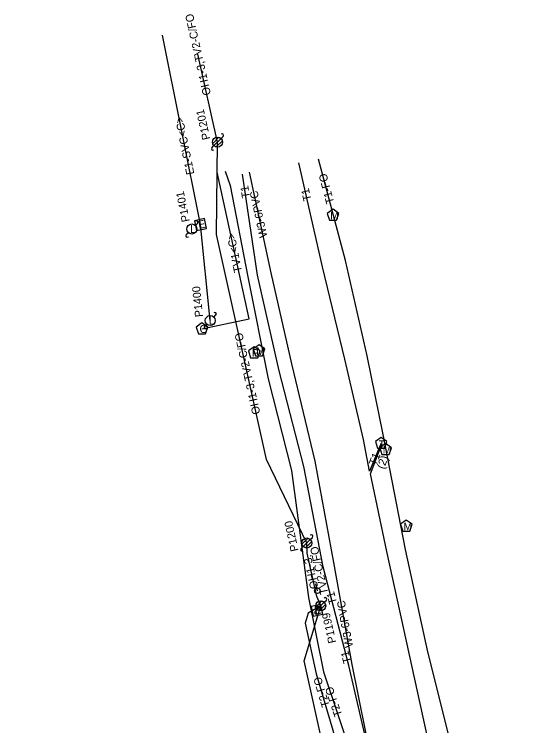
# Model space of a CAD drawing. Extents: x 2336688 to 2352634, y 362473 to 369571.
# Drawn here: x 2351896.3 to 2352159.1, y 369215.5 to 369570.9 of the extents above; entities that cross this region are included whole.
import ezdxf

# ---------------------------------------------------------------- set-up
doc = ezdxf.new("R2010")
doc.units = 0
for name, color, linetype in [('RD_EX_DV_Prop', 7, 'Continuous'), ('RD_EX_DV_TX_Prop', 7, 'Continuous'), ('RD_EX_RW', 7, 'Continuous'), ('RD_EX_RW_TX', 7, 'Continuous'), ('RD_HC_Data_Tic', 7, 'Continuous'), ('RD_PD_CstnLmt', 7, 'Continuous'), ('RD_PD_Final_TrvlWay', 7, 'Continuous'), ('RD_PD_PatLn4', 7, 'Continuous'), ('RD_SHT_ShtClip', 7, 'Continuous'), ('RD_Sketch2', 7, 'Continuous')]:
    doc.layers.add(name, color=color, linetype=linetype)

# ---------------------------------------------------------------- blocks, each defined once
blk = doc.blocks.new('GW')
at = {"layer": 'RD_HC_Data_Tic'}
blk.add_line((0, 0), (0, 5), dxfattribs=at)
blk.add_circle((0, 0), 2, dxfattribs=at)

msp = doc.modelspace()

# ---------------------------------------------------------------- linework, layer by layer
at = {"layer": 'RD_EX_RW_TX'}
for points in [[(2351882.96, 368961.6), (2351938.79, 368976.9), (2351987.72, 368987.57), (2352042.33, 368998.31), (2352089.62, 369005.75), (2352093.46, 369014.31), (2352094.98, 369015.98), (2352112.55, 369025.15), (2352149.58, 369043.65), (2352152.79, 369046.13), (2352158.47, 369042.65), (2352159.12, 369043.02), (2352158.82, 369043.5), (2352153.46, 369046.79), (2352149.48, 369061.78), (2352136.12, 369108.51), (2352124.11, 369157.73), (2352114.64, 369205.23), (2352102.73, 369252.4), (2352091.67, 369303.48), (2352080.48, 369361.01), (2352072.4, 369400.34), (2352061.58, 369447.94), (2352048.21, 369498.55)], [(2352099.24, 369013.18), (2352100.77, 369013.18), (2352102.01, 369010.35), (2352113.48, 369011.8), (2352144.5, 369021.33), (2352137.63, 369058.32), (2352126.61, 369104.63), (2352115.02, 369155.75), (2352104.18, 369202.36), (2352093.63, 369250.91), (2352082.32, 369302.6), (2352074.09, 369341.41), (2352079.44, 369355.35), (2352079.44, 369356.53), (2352079.15, 369355.79), (2352073.69, 369342.66), (2352070.62, 369358.43), (2352061.32, 369398.59), (2352050.18, 369444.73), (2352038.41, 369496.7)], [(2351989.99, 369413.72), (2352013.51, 369418.85), (2351997.53, 369492.08)], [(2352001.58, 369492.45), (2352004.02, 369485.34), (2352012.81, 369439.77), (2352023.11, 369388.83), (2352034.68, 369342.96), (2352043.16, 369279.52), (2352050.69, 369242.38), (2352066.16, 369196.28), (2352079.88, 369147.58), (2352091.56, 369098.6), (2352098.41, 369047.57), (2352103.47, 369016.03), (2352103.73, 369007.69), (2352104.69, 368996.59), (2352107.92, 368897.46), (2352108.57, 368885.58), (2352108.45, 368884.09), (2352110.04, 368883.31), (2352120.9, 368857.81), (2352128.32, 368840.02), (2352133.08, 368783.49)], [(2352099.24, 369013.18), (2352100.17, 369016.12), (2352103.97, 369041.01), (2352095.58, 369099.08), (2352084.55, 369148.38), (2352074.51, 369197.44), (2352063.29, 369245.58), (2352050.57, 369294.92), (2352040.76, 369344.96), (2352028.6, 369392.74), (2352017.72, 369440.57), (2352010.21, 369491.1)], [(2352049.25, 369275.42), (2352042.97, 369271.71), (2352041.48, 369266.72), (2352046.93, 369241.42), (2352057.49, 369205.93), (2352058.07, 369204.44), (2352057.07, 369203.93), (2352036.99, 369200.44), (2352017.18, 369199.37)]]:
    msp.add_lwpolyline(points, dxfattribs=at)
for points in [[(2351989.99, 369416.72), (2351987.14, 369414.65), (2351988.23, 369411.29), (2351991.76, 369411.29), (2351992.85, 369414.65)], [(2352079.44, 369359.53), (2352076.59, 369357.46), (2352077.68, 369354.11), (2352081.21, 369354.11), (2352082.3, 369357.46)]]:
    msp.add_lwpolyline(points, close=True, dxfattribs=at)
at = {"layer": 'RD_HC_Data_Tic'}
for p, q in [((2351995.33, 369506.4), (2351998.39, 369509.46)), ((2351995.97, 369505.28), (2351999.51, 369508.81)), ((2351997.09, 369504.63), (2352000.16, 369507.69)), ((2351999.51, 369508.81), (2352000.57, 369509.87)), ((2351994.91, 369504.22), (2351995.97, 369505.28)), ((2351986.72, 369465.41), (2351987.78, 369466.47)), ((2351982.13, 369460.81), (2351983.19, 369461.88)), ((2351995.9, 369419.66), (2351996.96, 369420.72)), ((2351991.3, 369415.06), (2351992.36, 369416.13)), ((2352039.89, 369306.15), (2352042.96, 369309.21)), ((2352040.54, 369305.03), (2352044.08, 369308.56)), ((2352044.08, 369308.56), (2352045.14, 369309.62)), ((2352039.48, 369303.96), (2352040.54, 369305.03)), ((2352041.66, 369304.38), (2352044.72, 369307.44)), ((2352046.84, 369274.77), (2352049.9, 369277.84)), ((2352047.48, 369273.65), (2352051.02, 369277.19)), ((2352051.02, 369277.19), (2352052.08, 369278.25)), ((2352046.42, 369272.59), (2352047.48, 369273.65)), ((2352048.6, 369273.01), (2352051.67, 369276.07))]:
    msp.add_line(p, q, dxfattribs=at)
for centre in [(2351997.74, 369507.05), (2351984.95, 369463.64), (2351994.13, 369417.89), (2352042.31, 369306.79), (2352049.25, 369275.42)]:
    msp.add_circle(centre, 2.5, dxfattribs=at)
for centre, start, end in [((2352000.04, 369510.4), 315, 135), ((2351995.44, 369503.69), 135, 315), ((2351987.25, 369467), 315, 135), ((2351982.66, 369460.28), 135, 315), ((2351996.43, 369421.25), 315, 135), ((2351991.83, 369414.53), 135, 315), ((2352044.61, 369310.15), 315, 135), ((2352040.01, 369303.43), 135, 315), ((2352051.55, 369278.78), 315, 135), ((2352046.95, 369272.06), 135, 315)]:
    msp.add_arc(centre, 0.75, start, end, dxfattribs=at)
at = {"layer": 'RD_PD_Final_TrvlWay'}
msp.add_lwpolyline([(2351994.13, 369417.89), (2351989.27, 369465.86), (2351970.26, 369560.53)], dxfattribs=at)
for points in [[(2351991.19, 369468.82), (2351986.3, 369467.78), (2351987.34, 369462.89), (2351992.23, 369463.93)], [(2352049.32, 369276.14), (2352044.43, 369275.1), (2352045.48, 369270.21), (2352050.37, 369271.25)]]:
    msp.add_lwpolyline(points, close=True, dxfattribs=at)
at = {"layer": 'RD_SHT_ShtClip'}
msp.add_line((2351997.74, 369507.05), (2351987.95, 369551.02), dxfattribs=at)
for points in [[(2352042.31, 369306.79), (2352022.23, 369348.43), (2351997.22, 369460.83), (2351997.74, 369507.05)], [(2352049.25, 369275.42), (2352047.36, 369280.12), (2352042.58, 369301.73), (2352042.31, 369306.79)], [(2352100.79, 369043.46), (2352081.67, 369064.82), (2352040.97, 369247.97), (2352049.25, 369275.42)]]:
    msp.add_lwpolyline(points, dxfattribs=at)
at = {"layer": 'RD_Sketch2'}
msp.add_lwpolyline([(2352123.62, 368989.01), (2352123.23, 368992.87), (2352110.76, 369051.44), (2352100.32, 369099.76), (2352090.2, 369149.12), (2352082.32, 369170.12), (2352074.84, 369197.41), (2352065.04, 369246.15), (2352055.85, 369297.1), (2352046.45, 369347.59), (2352034.9, 369396.24), (2352024.46, 369441.79), (2352013.71, 369492.08)], dxfattribs=at)
for points in [[(2352055.43, 369473.56), (2352052.53, 369471.45), (2352053.64, 369468.04), (2352057.23, 369468.04), (2352058.33, 369471.45)], [(2352016.07, 369404.81), (2352013.17, 369402.7), (2352014.28, 369399.29), (2352017.87, 369399.29), (2352018.97, 369402.7)], [(2352018.49, 369405.82), (2352015.59, 369403.71), (2352016.69, 369400.3), (2352020.28, 369400.3), (2352021.39, 369403.71)], [(2352081.64, 369356.48), (2352078.74, 369354.37), (2352079.85, 369350.96), (2352083.44, 369350.96), (2352084.54, 369354.37)], [(2352092, 369318.24), (2352089.1, 369316.13), (2352090.21, 369312.72), (2352093.79, 369312.72), (2352094.9, 369316.13)]]:
    msp.add_lwpolyline(points, close=True, dxfattribs=at)

# ---------------------------------------------------------------- block references
at = {"layer": 'RD_HC_Data_Tic', "xscale": 0.6933464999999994, "yscale": 0.6933464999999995, "rotation": 12.258911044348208}
msp.add_blockref('GW', (2352047.6, 369282.95), dxfattribs=at)

# ---------------------------------------------------------------- texts
at = {"layer": 'RD_EX_DV_Prop'}
msp.add_text('E1-SVC<C>', height=4, rotation=101.4111, dxfattribs=at).set_placement((2351986.21, 369491.18))
at = {"layer": 'RD_EX_DV_TX_Prop'}
for s, rotation, p in [('P1201', 102.5472, (2351994.19, 369508.64)), ('P1401', 101.3498, (2351983.92, 369467.56)), ('P1400', 95.7907, (2351990.54, 369419.84)), ('P1200', 102.4791, (2352038.28, 369303.04)), ('P1199', 102.4791, (2352057.04, 369257.16))]:
    msp.add_text(s, height=4, rotation=rotation, dxfattribs=at).set_placement(p)
at = {"layer": 'RD_EX_RW'}
for s, rotation, p in [('T1-FO', 104.7941, (2352056.03, 369476.78)), ('T1', 98.4582, (2352013.98, 369479.35)), ('T1', 102.7619, (2352044.67, 369478.12)), ('TV1<C>', 100.9276, (2352010, 369442.32)), ('T1', 68.9713, (2352076.89, 369345.11)), ('(2)', 68.9713, (2352080.82, 369343.42)), ('T1', 104.4325, (2352057.46, 369276.82)), ('T1', 104.4532, (2352064.59, 369247.24)), ('T2-FO', 106.5694, (2352053.77, 369225.45)), ('T2-FO', 108.5512, (2352060.04, 369220.79))]:
    msp.add_text(s, height=4, rotation=rotation, dxfattribs=at).set_placement(p)
at = {"layer": 'RD_EX_RW_TX'}
for s, height, p in [('C', 4, (2351988.76, 369411.72)), ('T', 3.75, (2352078.22, 369354.31))]:
    msp.add_text(s, height=height, dxfattribs=at).set_placement(p)
at = {"layer": 'RD_HC_Data_Tic'}
for p in [(2351984.14, 369461.71), (2351993.32, 369415.96)]:
    msp.add_text('L', height=4, rotation=360, dxfattribs=at).set_placement(p)
at = {"layer": 'RD_PD_CstnLmt'}
for rotation, p in [(102.0621, (2352022.66, 369459.77)), (100.2336, (2352065.48, 369254.97))]:
    msp.add_text('W3-6PVC', height=4, rotation=rotation, dxfattribs=at).set_placement(p)
at = {"layer": 'RD_PD_Final_TrvlWay'}
for p in [(2351988.5, 369463.65), (2352046.63, 369270.97)]:
    msp.add_text('E', height=4, rotation=12.0621, dxfattribs=at).set_placement(p)
at = {"layer": 'RD_PD_PatLn4'}
for s, rotation, p in [('OH1-3,TV2-C/FO', 102.5472, (2351994.49, 369530.86)), ('OH1-3,TV2-C/FO', 102.5472, (2352019.15, 369371.49)), ('TV2-C/FO', 102.4791, (2352053.07, 369281.6)), ('OH1-3,', 102.4791, (2352048.09, 369284.3))]:
    msp.add_text(s, height=4, rotation=rotation, dxfattribs=at).set_placement(p)
at = {"layer": 'RD_Sketch2'}
for p in [(2352054.06, 369468.52), (2352017.12, 369400.78), (2352080.27, 369351.44), (2352090.63, 369313.19)]:
    msp.add_text('M', height=3.75, dxfattribs=at).set_placement(p)
msp.add_text('P', height=3.75, rotation=360, dxfattribs=at).set_placement((2352014.92, 369399.88))

doc.saveas('drawing.dxf')
